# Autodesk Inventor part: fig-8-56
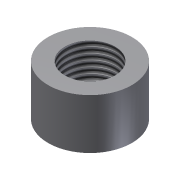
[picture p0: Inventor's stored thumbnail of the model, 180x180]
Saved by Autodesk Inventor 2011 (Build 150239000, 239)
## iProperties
Shininess: 77.0
Length Units: 11269
Angle Units: 11279
Time Units: 11290
Mass Units: 11283
Length Display Precision: 3
Angle Display Precision: 2
Compacted: True
Created: 2002-01
Part Number: fig-8-56
Document SubType Name: Modeling
Designer: ***
Density: 1 g/cm^3
Density: 0.0
Volumn: 0.0
Area: 0.0
PropertySet Name: Model Information
Control State: 0
Master: False
Checked Out: False
Author: ***
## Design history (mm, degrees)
sketch "Sketch1"
  geometry: C1 r 25 at (0, 0); C2 r 15 at (0, 0)
  constraints: 2 centre point, 1 coincident
  dimensions: "d0" = 50 diameter of C1; "d1" = 30 diameter of C2
extrude "Extrusion1" new body sketch "Sketch1" distance "d2" = 30; taper "d3" = 0 deg
thread "Thread5" dims "d12" = 10, "d13" = 0
body "Solid1"
